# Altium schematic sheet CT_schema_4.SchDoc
size 283 x 174 mm
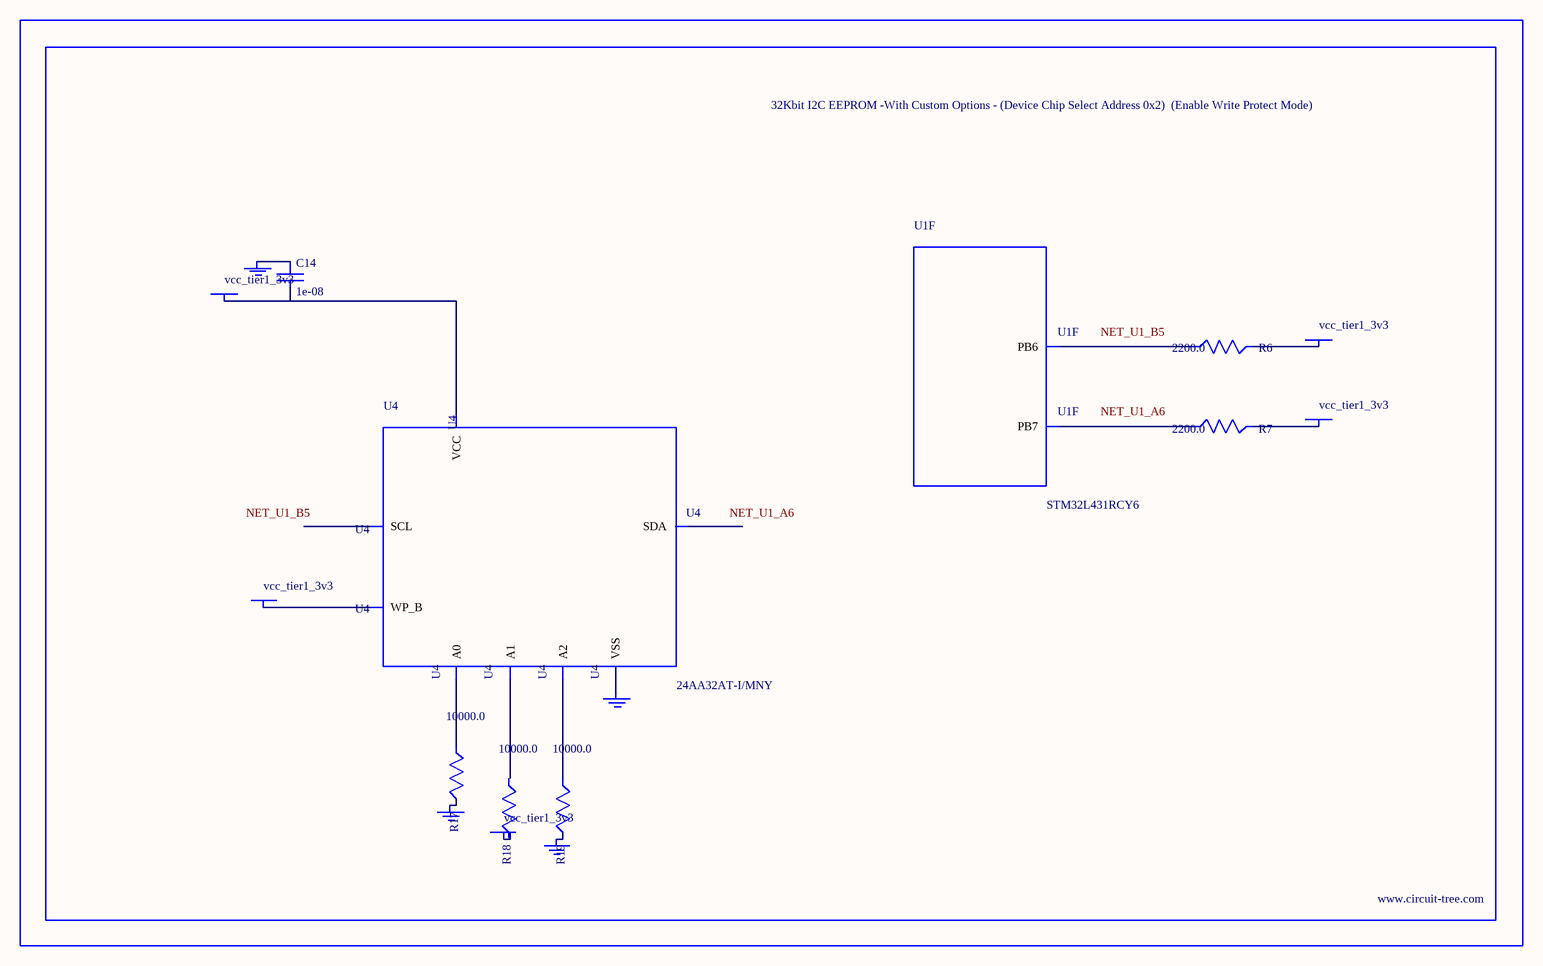
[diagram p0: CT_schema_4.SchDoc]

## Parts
BORDER3  (no value)
C14  1e-08  [C0402]
GND_INSTANCE_3_0  (no value)
GND_INSTANCE_3_1  (no value)
GND_INSTANCE_3_2  (no value)
GND_INSTANCE_3_3  (no value)
POWER_INSTANCE_3_0  vcc_tier1_3v3
POWER_INSTANCE_3_1  vcc_tier1_3v3
POWER_INSTANCE_3_2  vcc_tier1_3v3
POWER_INSTANCE_3_3  vcc_tier1_3v3
POWER_INSTANCE_3_4  vcc_tier1_3v3
R6  2200.0  [R0603]
R7  2200.0  [R0603]
R17  10000.0  [R0603]
R18  10000.0  [R0603]
R19  10000.0  [R0603]
U1  STM32L431RCY6  [WLCSP64]  (part F of 8)
U4  24AA32AT-I/MNY  [TDFN-8/6MM]

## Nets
NetC14_1: C14.1 GND_INSTANCE_3_2.0(GND)
NetC14_2: C14.2 POWER_INSTANCE_3_2.0(PWR) U4.8(VCC)
NetGND_INSTANCE_3_0_0: GND_INSTANCE_3_0.0(GND) R17.2
NetGND_INSTANCE_3_1_0: GND_INSTANCE_3_1.0(GND) R19.2
NetGND_INSTANCE_3_3_0: GND_INSTANCE_3_3.0(GND) U4.4(VSS)
NetPOWER_INSTANCE_3_1_0: POWER_INSTANCE_3_1.0(PWR) U4.7(WP_B)
NetPOWER_INSTANCE_3_3_0: POWER_INSTANCE_3_3.0(PWR) R6.2
NetPOWER_INSTANCE_3_4_0: POWER_INSTANCE_3_4.0(PWR) R7.2
NetR6_1: R6.1 U1.B5(PB6)
NetR7_1: R7.1 U1.A6(PB7)
NetR17_1: R17.1 U4.1(A0)
NetR19_1: R19.1 U4.3(A2)

Not connected (* = marked no-connect by the designer): POWER_INSTANCE_3_0 0(PWR); R18 1 2; U4 2(A1) 5(SDA) 6(SCL)

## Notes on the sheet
- Labels drawn without touching a wire or pin: NET_U1_A6, NET_U1_B5

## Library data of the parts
BORDER3 = BORDER_PAGE3
C14 = C0402C103K3RAC
GND_INSTANCE_3_0-GND_INSTANCE_3_3 = GND
POWER_INSTANCE_3_0-POWER_INSTANCE_3_4 = PWR
R6 R7 = RC0603JR-072K2L
R17-R19 = RC0603JR-0710KL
